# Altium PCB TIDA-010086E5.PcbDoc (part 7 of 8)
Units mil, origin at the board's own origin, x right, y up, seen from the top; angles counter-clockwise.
Board outline 6400 x 6200 mil, 6 copper layers (Top Layer, Power, AGND, Signal, PGND, Bottom Layer), stack 70.536 mil thick; 717 components, 376 nets, 2259 pads, 2183 vias.
Unrouted connection lines stored in the file: 1424.
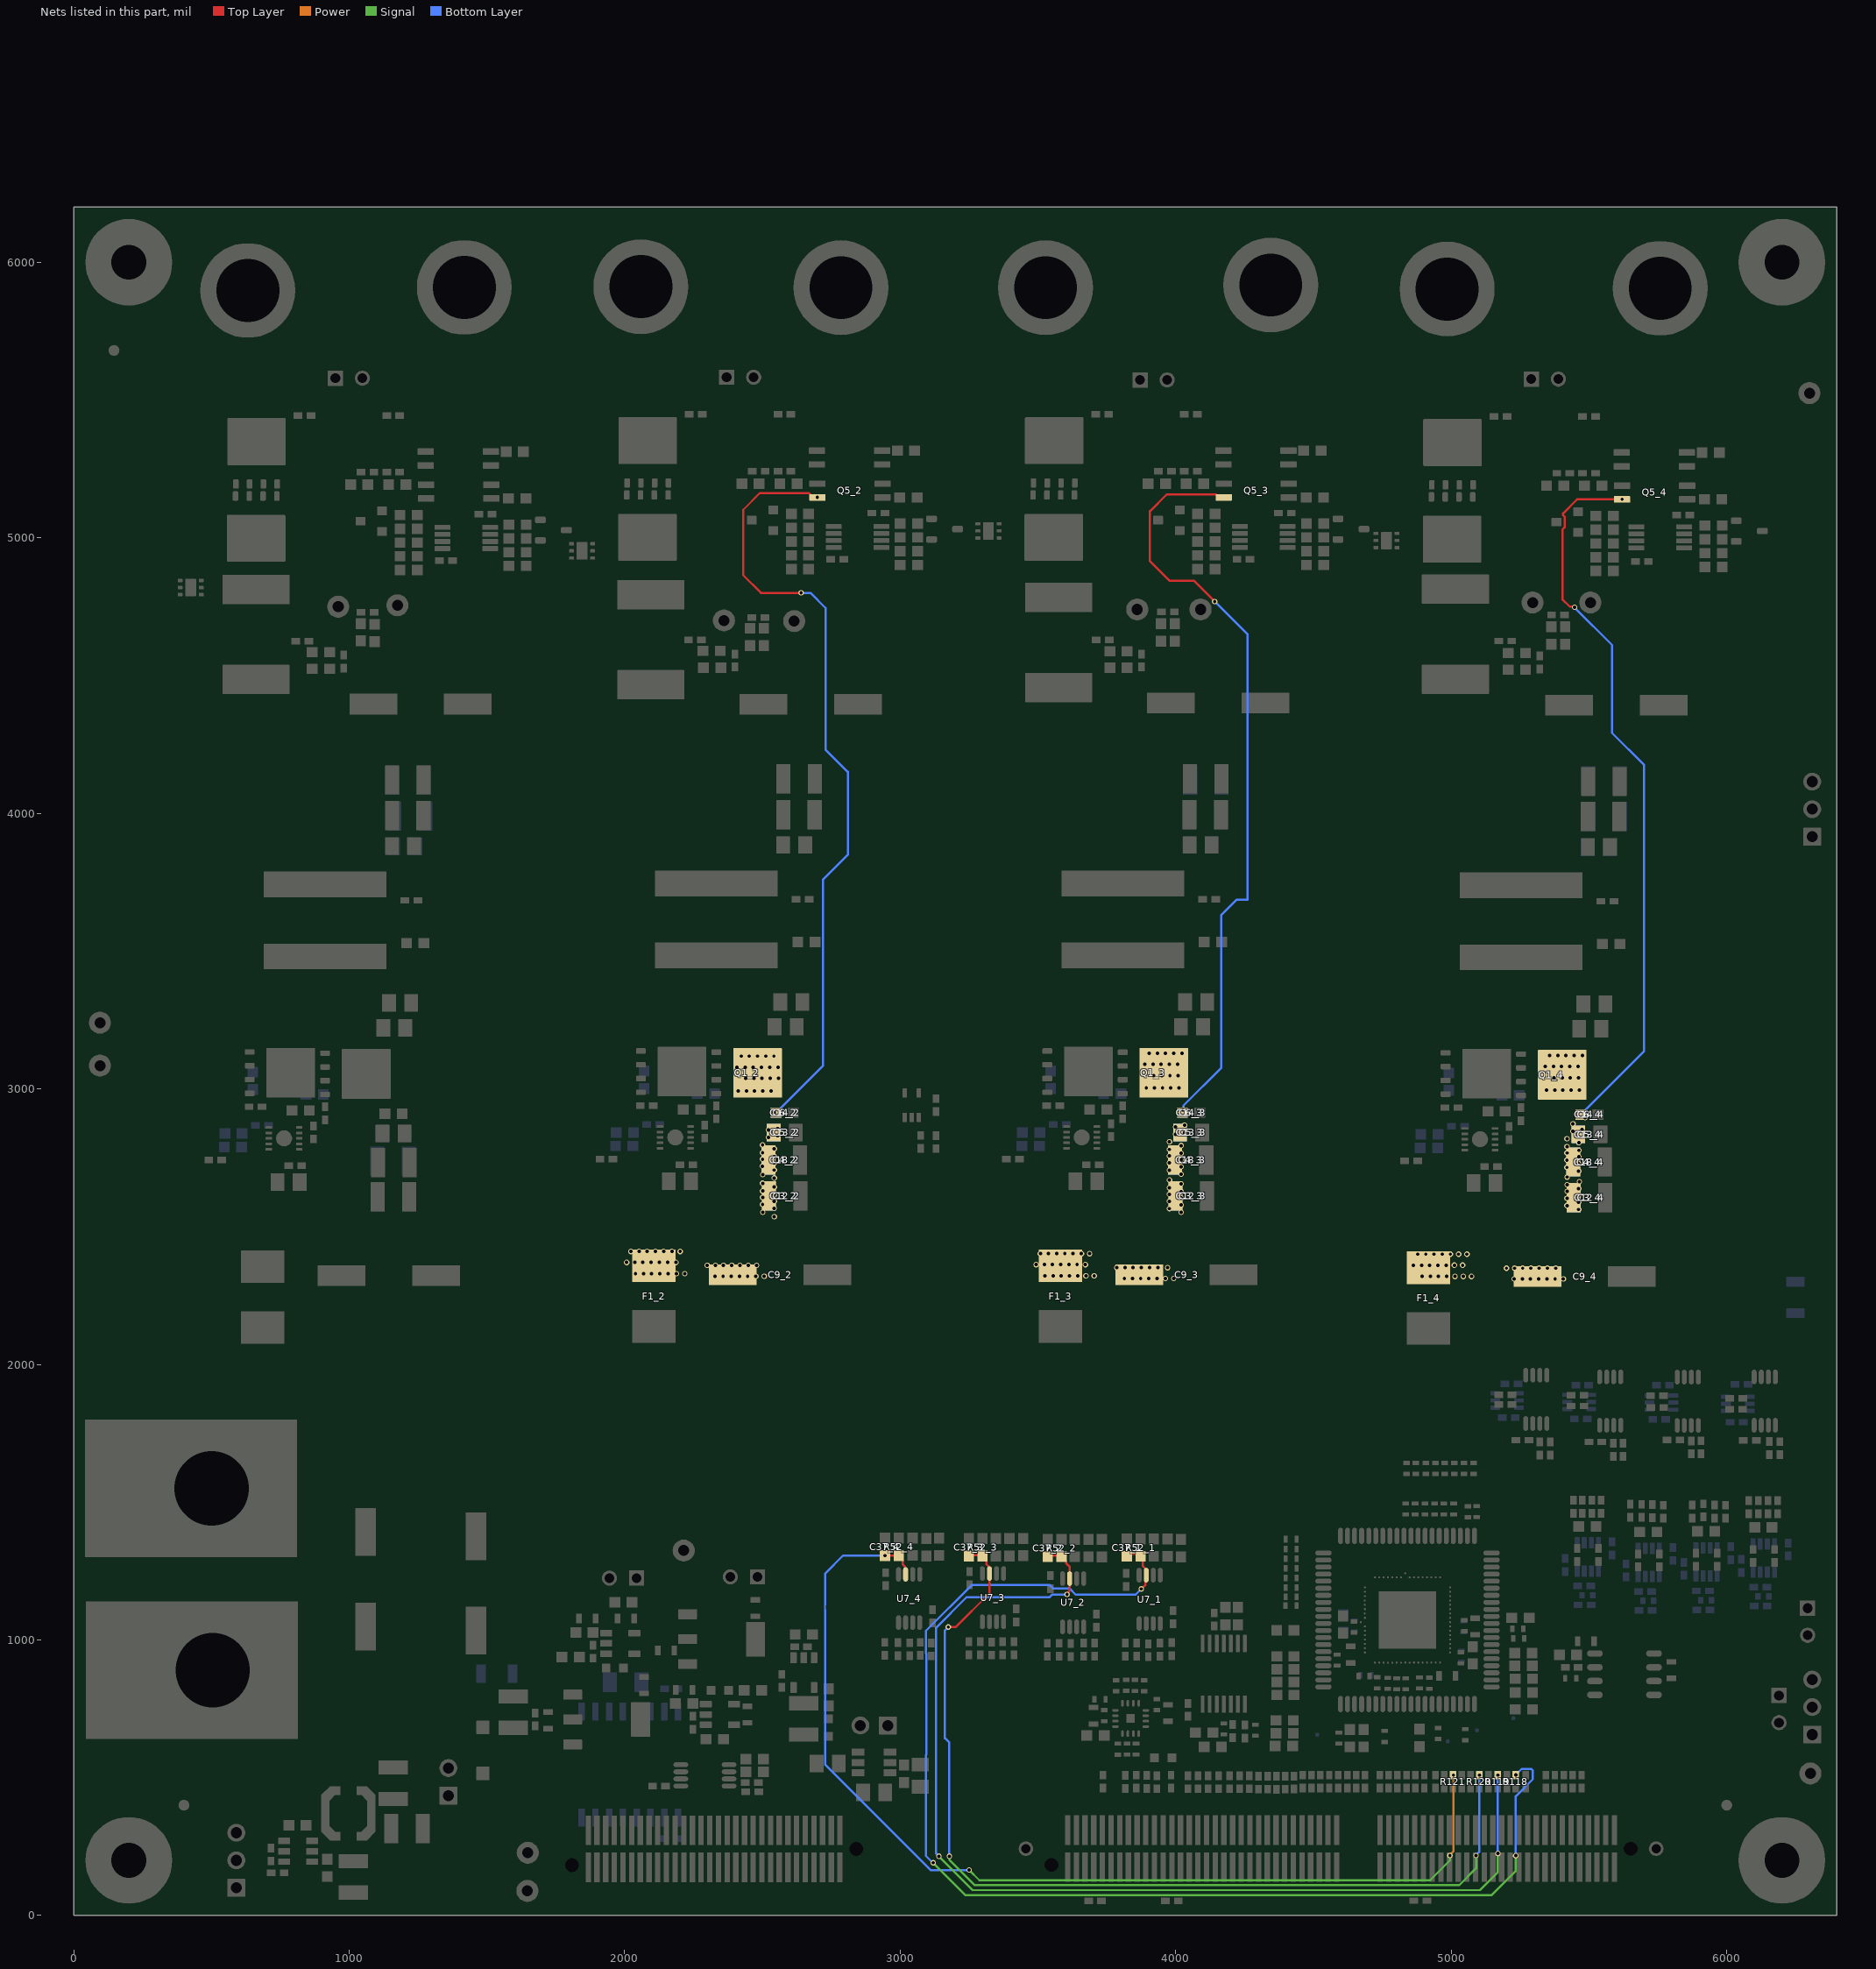
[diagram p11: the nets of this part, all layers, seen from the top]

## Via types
v1: diameter 20, hole 12.5, Top Layer to Bottom Layer, 1408 vias
v2: diameter 20, hole 12, Top Layer to Bottom Layer, tented both sides, 775 vias

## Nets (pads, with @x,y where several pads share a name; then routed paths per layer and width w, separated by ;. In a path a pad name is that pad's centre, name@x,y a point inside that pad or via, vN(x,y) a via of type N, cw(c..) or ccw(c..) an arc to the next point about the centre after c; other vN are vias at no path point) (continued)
VIN_2: C3_2.1 C4_2.1 C5_2.1 C6_2.1 C9_2.1 C12_2.1 C13_2.1 C14_2.1 C18_2.1 F1_2.1 Q1_2.5 Q1_2.6 Q1_2.7 Q1_2.8 Q1_2.9@2481.97,3057.91 Q5_2.4 | length 2861.8
  Top Layer w7.87: v2(2640,4800) 2494.23,4800 2430,4864.23 2430,5101.61 2490.35,5161.96 2668.85,5161.96 2674.71,5156.1 2674.71,5153.15 2681.2,5146.66 v2(2699.24,5146.66)
  Bottom Layer w7.87: C14_2.1@2549.17,2913.31 2550.16,2913.31 2564.92,2928.07 2564.92,2929.06 2720,3084.13 2720,3760 2810,3850 2810,4150 2728.35,4231.65 2728.35,4745.4 2673.75,4800 v2(2640,4800)
  other v1: 2327.28,2319.91 2356.97,2319.91 2386.1,2319.91 2416.1,2319.91 2446.1,2319.91 2476.1,2319.91 2506.1,2319.91 2038.86,2329.06 2068.54,2329.06 2097.68,2329.06 2127.68,2329.06 2157.68,2329.06 2187.68,2329.06 2217.68,2329.06 2299.53,2359.06 2329.21,2359.06 2358.35,2359.06 2388.35,2359.06 2418.35,2359.06 2448.35,2359.06 2478.35,2359.06 2006.83,2369.91 2036.52,2369.91 2065.65,2369.91 2095.65,2369.91 2125.65,2369.91 2155.65,2369.91 2185.65,2369.91 2022.28,2409.91 2051.97,2409.91 2081.1,2409.91 2111.1,2409.91 2141.1,2409.91 2171.1,2409.91 2201.1,2409.91 2542.93,2535.61 2500.89,2551.68 2542.43,2566.45 2500.12,2580.25 2542.68,2592.1 2500.37,2605.89 2542.68,2615.52 2500.37,2629.32 2542.68,2643.58 2500.37,2657.38 2542.93,2676.33 2500.89,2688.22 2542.68,2705.25 2499.87,2719.11 2542.93,2730.89 2500.12,2744.76 2542.93,2754.32 2500.12,2768.19 2542.93,2782.38 2500.12,2796.25 2521.81,2823.82 2554.99,2829.68 2521.81,2850.48 2554.99,2856.34 2541.62,2914.26 2412.07,2992.72 2441.76,2992.72 2470.89,2992.72 2500.89,2992.72 2530.89,2992.72 2439.18,3037.79 2468.87,3037.79 2498,3037.79 2528,3037.79 2558,3037.79 2407.15,3078.63 2436.84,3078.63 2465.97,3078.63 2495.97,3078.63 2525.97,3078.63 2555.97,3078.63 2422.61,3118.63 2452.29,3118.63 2481.43,3118.63 2511.43,3118.63 2541.43,3118.63
VIN_3: C3_3.1 C4_3.1 C5_3.1 C6_3.1 C9_3.1 C12_3.1 C13_3.1 C14_3.1 C18_3.1 F1_3.1 Q1_3.5 Q1_3.6 Q1_3.7 Q1_3.8 Q1_3.9@3956.97,3057.91 Q5_3.4 | length 2799.5
  Top Layer w7.87: v2(4141.48,4768.86) 4065.68,4844.66 3976.71,4844.66 3906.32,4915.04 3906.32,5096.44 3967.31,5157.43 4145.43,5157.43 4156.52,5146.34 Q5_3.4@4174.24,5146.34
  Bottom Layer w7.87: C14_3.1@4024.17,2913.31 4025.16,2913.31 C14_3.1@4030.83,2918.98 ; C14_3.1@4026.06,2925.01 C14_3.1@4027.04,2925.01 ; v1(4026.26,2923.56) 4028.24,2925.54 4028.24,2939.21 4165.29,3076.26 4165.29,3631.14 4219.99,3685.85 4260,3685.85 4260,4650.34 v2(4141.48,4768.86)
  other v1: 3813.58,2311.92 3843.27,2311.92 3872.4,2311.92 3902.4,2311.92 3932.4,2311.92 3962.4,2311.92 3992.4,2311.92 3525.16,2321.07 3554.84,2321.07 3583.98,2321.07 3613.98,2321.07 3643.98,2321.07 3673.98,2321.07 3703.98,2321.07 3785.83,2351.07 3815.51,2351.07 3844.65,2351.07 3874.65,2351.07 3904.65,2351.07 3934.65,2351.07 3970.3,2351.07 3493.13,2361.92 3522.81,2361.92 3551.95,2361.92 3581.95,2361.92 3611.95,2361.92 3641.95,2361.92 3671.95,2361.92 3508.58,2401.92 3538.27,2401.92 3567.4,2401.92 3597.4,2401.92 3627.4,2401.92 3657.4,2401.92 3687.4,2401.92 4019.32,2551.49 3977,2565.29 4019.32,2578.15 3977,2591.95 4019.56,2603.8 3977.25,2617.6 4019.56,2627.23 3977.25,2641.02 4019.56,2655.29 3977.25,2669.08 4019.56,2690.29 3976.75,2704.15 4019.56,2716.95 3976.75,2730.82 4019.81,2742.6 3977,2756.47 4019.81,2766.02 3977,2779.89 4019.81,2794.08 3977,2807.95 3998.7,2835.52 4031.88,2841.38 3998.7,2862.18 4031.88,2868.05 3893.05,3003.2 3922.74,3003.2 3951.87,3003.2 3981.87,3003.2 4011.87,3003.2 3920.16,3048.28 3949.84,3048.28 3978.98,3048.28 4008.98,3048.28 3888.13,3089.12 3917.81,3089.12 3946.95,3089.12 3976.95,3089.12 4006.95,3089.12 3903.58,3129.12 3933.27,3129.12 3962.4,3129.12 3992.4,3129.12 4022.4,3129.12
VIN_4: C3_4.1 C4_4.1 C5_4.1 C6_4.1 C9_4.1 C12_4.1 C13_4.1 C14_4.1 C18_4.1 F1_4.1 Q1_4.5 Q1_4.6 Q1_4.7 Q1_4.8 Q1_4.9@5402.75,3051.07 Q5_4.4 | length 2651.1
  Top Layer w7.87: v2(5447.82,4747.79) 5445.5,4750.11 5430.17,4750.11 5403.59,4776.68 5403.59,5030.09 5411.16,5037.66 5411.16,5076.54 5405.56,5082.14 5405.56,5088.66 5456.4,5139.5 Q5_4.4@5620.02,5139.5 v2(5620.02,5139.82)
  Bottom Layer w7.87: v2(5447.82,4747.79) 5447.82,4746.6 5583.34,4611.09 5583.34,4291.66 5700,4175 5700,3136.52 5485.7,2922.22 5485.7,2921.23 5470.94,2906.47 C14_4.1@5469.95,2906.47
  other v1: 5227.96,2310 5257.65,2310 5286.78,2310 5316.78,2310 5346.78,2310 5376.78,2310 5406.78,2310 4894.54,2319.15 4924.22,2319.15 4953.36,2319.15 4983.36,2319.15 5013.36,2319.15 5043.36,2319.15 5073.36,2319.15 5200.21,2349.15 5229.89,2349.15 5259.03,2349.15 5289.03,2349.15 5319.03,2349.15 5349.03,2349.15 5379.03,2349.15 4862.51,2360 4892.19,2360 4921.33,2360 4951.33,2360 4981.33,2360 5011.33,2360 5041.33,2360 4877.96,2400 4907.65,2400 4936.78,2400 4966.78,2400 4996.78,2400 5026.78,2400 5056.78,2400 5462.26,2562.22 5419.95,2576.02 5462.26,2588.88 5419.95,2602.68 5462.51,2614.53 5420.2,2628.33 5462.51,2637.95 5420.2,2651.75 5465.12,2663.08 5420.2,2679.81 5462.51,2701.02 5419.7,2714.88 5462.51,2727.68 5419.7,2741.54 5462.76,2753.33 5419.95,2767.19 5462.76,2776.75 5419.95,2790.62 5462.76,2804.81 5419.95,2818.68 5441.64,2846.25 5474.82,2852.11 5441.64,2872.91 5485.7,2895.83 5346.3,2995.29 5375.98,2995.29 5405.12,2995.29 5435.12,2995.29 5465.12,2995.29 5373.4,3040.36 5403.09,3040.36 5432.22,3040.36 5462.22,3040.36 5341.38,3081.21 5371.06,3081.21 5400.19,3081.21 5430.19,3081.21 5460.19,3081.21 5356.83,3121.21 5386.51,3121.21 5415.65,3121.21 5445.65,3121.21 5475.65,3121.21
VoutP1: C37_1.1 R52_1.2 R118.1 U7_1.7 | length 4585.6
  Top Layer w7.87: C37_1.1@3816.27,1311.67 3866.27,1311.67 3879.97,1297.97 3879.97,1268.78 3890.62,1258.13 3890.62,1236.77 U7_1.7@3892.5,1234.89 3890.62,1233 3890.62,1200.62 v2(3875,1185)
  Signal w7.87: v2(3119.71,190.92) 3119.71,189.79 3235.63,73.87 5146.41,73.87 5234.07,161.53 v2(5234.07,216.97)
  Bottom Layer w7.87: v2(3119.71,190.92) 3118.58,190.92 3093.24,216.26 3093.24,582.77 3094.21,583.74 3094.21,950.25 3093.24,951.22 3093.24,1032.77 3259.33,1198.85 3542.46,1198.85 3554.51,1186.81 3614.03,1186.81 3636.61,1164.24 3854.24,1164.24 v2(3875,1185) ; v2(5234.07,216.97) 5233.87,217.17 5233.87,432.45 5295.53,494.11 5295.53,526.16 5289.68,532.02 5255.99,532.02 v2(5234.07,510.1)
VoutP2: C37_2.1 R52_2.2 R119.1 U7_2.7 | length 4024.4
  Top Layer w7.87: C37_2.1@3537.7,1306.09 3587.7,1306.09 3587.7,1298.55 3602.44,1283.81 3602.44,1277.5 3609.35,1270.58 3610.05,1270.58 3614.67,1265.97 U7_2.7@3614.67,1222.56 3614.67,1177.91 3605,1168.25 v2(3605,1165)
  Signal w7.87: v2(3140,214.63) 3262.88,91.75 5103.62,91.75 5168.92,157.05 v2(5168.92,225)
  Bottom Layer w7.87: v2(3140,214.63) 3140,215.3 3130,225.3 3130,1044.25 3240.98,1155.23 3542.46,1155.23 3552.23,1165 v2(3605,1165) ; v2(5168.92,225) v2(5168.92,509.13)
VoutP3: C37_3.1 R52_3.2 R120.1 U7_3.7 | length 3573
  Top Layer w7.87: v2(3174.16,1046.42) 3201.06,1046.42 3323.72,1169.08 U7_3.7@3323.72,1241.1 ; C37_3.1@3248.72,1307.07 3298.72,1307.07 3312.42,1293.37 3312.42,1275.39 3322.24,1265.57 U7_3.7@3322.24,1241.1
  Signal w7.87: v2(3178.14,214.63) 3179.39,213.38 3179.39,200.52 3200.46,179.45 3270.29,109.62 5028.56,109.62 5090,171.06 v2(5090,217.27)
  Bottom Layer w7.87: v2(3174.16,1046.42) 3162.02,1034.28 3162.02,643.51 3178.14,627.39 v2(3178.14,214.63) ; v2(5090,217.27) 5090,219.98 5102.07,232.05 v2(5102.07,509.13)
VoutP4: C37_4.1 R52_4.2 R121.1 U7_4.7 | length 3852.8
  Top Layer w7.87: v2(2944.4,1306.09) R52_4.2@2994.39,1306.09 3009.16,1291.32 3009.16,1273.34 3017.51,1264.99 3017.51,1239.79 U7_4.7@3019.39,1237.91
  Signal w7.87: v2(3250,165) 3287.37,127.63 4922.95,127.63 4995,199.69 v2(4995,217.27)
  Power w7.87: v2(4995,217.27) 4995,219.98 5008.04,233.02 v2(5008.04,509.13)
  Bottom Layer w7.87: v2(2944.4,1306.09) 2792.83,1306.09 2727.87,1241.12 2727.87,1128.6 2726.74,1127.47 2726.74,1108.52 2727.87,1107.39 2727.87,546.82 3109.95,164.75 3249.75,164.75 v2(3250,165)
pads on no net: FID1.1 FID2.1 FID3.1 H1.1 H2.1 H3.1 H4.1 H5.0 H6.0 H7.0 H8.0 J13.1 J13.2 J13.3 J13.4 J13.5 J13.6 J13.8 J13.9 J13.11 J13.14 J13.17 J13.20 J13.23 J13.24 J13.26 J13.27 J13.32 J13.34 J13.36 J13.40 J13.41 J13.42 J13.43 J13.44 J13.58 J13.60 J13.62 J13.63 J13.64 J13.66 J13.76 J13.78 J13.86 J13.88 J13.89 J13.90 J13.91 J13.92 J13.93 J13.94 J13.95 J13.106 J13.107 J13.108 J13.109 J13.110 J13.113 J13.114 J13.115 J13.116 J13.117 J13.118 J13.119 J13.120 J13.181 J13.182 J13.185 J13.186 J14.61 J14.62 J14.121 J14.122 J14.123 J14.124 J14.125 J14.126 J14.127 J14.128 J14.129 J14.130 J14.131 J14.132 J14.133 J14.134 J14.136 J14.137 J14.138 J14.139 J14.140 J14.141 J14.142 J14.143 J14.144 J14.145 J14.146 J14.147 J14.148 J14.149 J14.150 J14.151 J14.152 J14.153 J14.154 J14.155 J14.156 J14.159 J14.160 J14.161 J14.162 J14.163 J14.164 J14.165 J14.166 J14.167 J14.168 J14.169 J14.170 J14.171 J14.172 J14.173 J14.174 J14.175 J14.176 J14.177 J14.178 LBL1.0 Q1_1.9@1007.32,2997.24 Q1_1.9@1007.32,3054.33 Q1_1.9@1007.32,3111.42 Q1_1.9@1043.94,3054.33 Q1_1.9@1077.4,2997.24 Q1_1.9@1077.4,3054.33 Q1_1.9@1077.4,3111.42 Q1_2.9@2427.44,3000.83 Q1_2.9@2427.44,3057.91 Q1_2.9@2427.44,3115 Q1_2.9@2464.06,3057.91 Q1_2.9@2497.52,3000.83 Q1_2.9@2497.52,3057.91 Q1_2.9@2497.52,3115 Q1_3.9@3902.44,3000.83 Q1_3.9@3902.44,3057.91 Q1_3.9@3902.44,3115 Q1_3.9@3939.06,3057.91 Q1_3.9@3972.52,3000.83 Q1_3.9@3972.52,3057.91 Q1_3.9@3972.52,3115 Q1_4.9@5348.22,2993.99 Q1_4.9@5348.22,3051.07 Q1_4.9@5348.22,3108.16 Q1_4.9@5384.83,3051.07 Q1_4.9@5418.3,2993.99 Q1_4.9@5418.3,3051.07 Q1_4.9@5418.3,3108.16 Q2_1.9@568.72,5073.35 Q2_1.9@609.76,4971.18 Q2_1.9@609.76,5016.46 Q2_1.9@609.76,5061.73 Q2_1.9@662.13,4971.18 Q2_1.9@662.13,5011.14 Q2_1.9@662.13,5016.46 Q2_1.9@662.13,5061.73 Q2_1.9@714.49,4971.18 Q2_1.9@714.49,5016.46 Q2_1.9@714.49,5061.73 Q2_1.9@755.53,5073.35 Q2_2.9@1988.84,5076.93 Q2_2.9@2029.88,4974.76 Q2_2.9@2029.88,5020.04 Q2_2.9@2029.88,5065.31 Q2_2.9@2082.24,4974.76 Q2_2.9@2082.24,5014.72 Q2_2.9@2082.24,5020.04 Q2_2.9@2082.24,5065.31 Q2_2.9@2134.61,4974.76 Q2_2.9@2134.61,5020.04 Q2_2.9@2134.61,5065.31 Q2_2.9@2175.65,5076.93 Q2_3.9@3463.84,5076.93 Q2_3.9@3504.88,4974.76 Q2_3.9@3504.88,5020.04 Q2_3.9@3504.88,5065.31 Q2_3.9@3557.24,4974.76 Q2_3.9@3557.24,5014.72 Q2_3.9@3557.24,5020.04 Q2_3.9@3557.24,5065.31 Q2_3.9@3609.61,4974.76 Q2_3.9@3609.61,5020.04 Q2_3.9@3609.61,5065.31 Q2_3.9@3650.65,5076.93 Q2_4.9@4909.62,5070.09 Q2_4.9@4950.66,4967.93 Q2_4.9@4950.66,5013.2 Q2_4.9@4950.66,5058.48 Q2_4.9@5003.02,4967.93 Q2_4.9@5003.02,5007.89 Q2_4.9@5003.02,5013.2 Q2_4.9@5003.02,5058.48 Q2_4.9@5055.39,4967.93 Q2_4.9@5055.39,5013.2 Q2_4.9@5055.39,5058.48 Q2_4.9@5096.43,5070.09 Q3_1.9@570.06,5273.74 Q3_1.9@611.1,5285.35 Q3_1.9@611.1,5330.63 Q3_1.9@611.1,5375.91 Q3_1.9@663.46,5285.35 Q3_1.9@663.46,5330.63 Q3_1.9@663.46,5335.94 Q3_1.9@663.46,5375.91 Q3_1.9@715.83,5285.35 Q3_1.9@715.83,5330.63 Q3_1.9@715.83,5375.91 Q3_1.9@756.87,5273.74 Q3_2.9@1990.18,5277.32 Q3_2.9@2031.22,5288.94 Q3_2.9@2031.22,5334.21 Q3_2.9@2031.22,5379.49 Q3_2.9@2083.58,5288.94 Q3_2.9@2083.58,5334.21 Q3_2.9@2083.58,5339.53 Q3_2.9@2083.58,5379.49 Q3_2.9@2135.95,5288.94 Q3_2.9@2135.95,5334.21 Q3_2.9@2135.95,5379.49 Q3_2.9@2176.99,5277.32 Q3_3.9@3465.18,5277.32 Q3_3.9@3506.22,5288.94 Q3_3.9@3506.22,5334.21 Q3_3.9@3506.22,5379.49 Q3_3.9@3558.58,5288.94 Q3_3.9@3558.58,5334.21 Q3_3.9@3558.58,5339.53 Q3_3.9@3558.58,5379.49 Q3_3.9@3610.94,5288.94 Q3_3.9@3610.94,5334.21 Q3_3.9@3610.94,5379.49 Q3_3.9@3651.99,5277.32 Q3_4.9@4910.96,5270.48 Q3_4.9@4952,5282.1 Q3_4.9@4952,5327.37 Q3_4.9@4952,5372.65 Q3_4.9@5004.36,5282.1 Q3_4.9@5004.36,5327.37 Q3_4.9@5004.36,5332.69 Q3_4.9@5004.36,5372.65 Q3_4.9@5056.72,5282.1 Q3_4.9@5056.72,5327.37 Q3_4.9@5056.72,5372.65 Q3_4.9@5097.77,5270.48 Q4_1.9@733.5,3001.77 Q4_1.9@733.5,3058.86 Q4_1.9@733.5,3115.94 Q4_1.9@770.12,3058.86 Q4_1.9@803.58,3001.77 Q4_1.9@803.58,3058.86 Q4_1.9@803.58,3115.94 Q4_2.9@2153.62,3005.35 Q4_2.9@2153.62,3062.44 Q4_2.9@2153.62,3119.53 Q4_2.9@2190.24,3062.44 Q4_2.9@2223.7,3005.35 Q4_2.9@2223.7,3062.44 Q4_2.9@2223.7,3119.53 Q4_3.9@3628.62,3005.35 Q4_3.9@3628.62,3062.44 Q4_3.9@3628.62,3119.53 Q4_3.9@3665.24,3062.44 Q4_3.9@3698.7,3005.35 Q4_3.9@3698.7,3062.44 Q4_3.9@3698.7,3119.53 Q4_4.9@5074.4,2998.52 Q4_4.9@5074.4,3055.6 Q4_4.9@5074.4,3112.69 Q4_4.9@5111.02,3055.6 Q4_4.9@5144.48,2998.52 Q4_4.9@5144.48,3055.6 Q4_4.9@5144.48,3112.69 R151.1 SH-J1.0 SH-J2.0 SH-J3.0 U1_1.7@424.52,4801.64 U1_1.7@424.52,4837.07 U1_2.7@1845,4935 U1_2.7@1845,4970.43 U1_3.7@3320,5007.28 U1_3.7@3320,5042.72 U1_4.7@4765,4972.28 U1_4.7@4765,5007.72 U3_1.2 U3_2.2 U3_3.2 U3_4.2 U5_1.1 U5_2.1 U5_3.1 U5_4.1 U6_1.2 U6_1.3 U6_2.2 U6_2.3 U6_3.2 U6_3.3 U6_4.2 U6_4.3 U9.4 U11.4 U15.41 U15.42 U15.43 U15.44 U15.45 U15.46 U18.1 U18.3 U18.7 U18.8 U20.1 U20.5 U22.4 U22.5 U22.11 U22.14

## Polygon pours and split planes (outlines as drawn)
PGND on Top Layer "TOP_LAYER_PGND_P274" (solid, remove dead copper, pour order 274): 0,6173.76 0,3.76 1510.39,3.76 1519.56,1646.22 4659.4,1646.22 5224.69,2203.76 6400,2203.76 6400,6203.71
5VD on Top Layer "TOP_LAYER_5VD_P127" (solid, remove dead copper, pour order 127): 2434.66,1100.2 2434.66,920.74 2637.87,920.74 2637.87,1100.2
AGND on Top Layer "TOP_LAYER_AGND_P273" (solid, remove dead copper, pour order 273): 1515,2227.77 1515,0.95 6400,0.95 6400,2227.77
Source_1 on Top Layer "TOP_LAYER_SOURCE_1_P272" (solid, remove dead copper, pour order 272): 454.52,5229.08 454.52,5124.49 893.97,5124.49 893.97,5229.08
SW_1 on Top Layer "TOP_LAYER_SW_1_P130" (solid, remove dead copper, pour order 130): 950,3156.51 950,3009.08 893.82,3009.08 890,3005.27 890,2964.08 818.54,2964.08 818.54,2900 770.12,2900 772.84,2959.79 697.57,2974.08 694.02,3061.22 694.02,3147.63 545.07,3296.58 545.07,3642.84 1241.48,3642.84 1241.48,3364.08 1110,3364.08 1110,3270 1135.12,3270 1162.57,3242.55 1162.57,3174.08 967.57,3174.08
V_HV on Top Layer "V_HV_Top" (solid, remove dead copper, pour order 143): 27.16,2235.04 27.16,1290 1836.73,1290 2236.54,1660 4633.7,1660 4910.47,1936.77 5002.69,2045 4999.96,2235.04
VIN_4 on Top Layer "TOP_LAYER_VIN_4_P136" (solid, remove dead copper, pour order 136): 4917.42,2580.83 4805.42,2527.49 4805.42,2246.66 4804.58,2245.83 5495.42,2245.83 5495.42,3153.04 5290.42,3153.04 5290.42,2580.83
VIN_3 on Top Layer "TOP_LAYER_VIN_3_P137" (solid, remove dead copper, pour order 137): 3471.64,2587.67 3359.64,2534.33 3359.64,2253.5 3359.64,2235.04 4049.64,2235.04 4049.64,3159.87 3844.64,3159.87 3844.64,2587.67
VIN_2 on Top Layer "TOP_LAYER_VIN_2_P140" (solid, remove dead copper, pour order 140): 1994.88,2590.11 1882.88,2536.78 1882.88,2255.94 1882.05,2255.11 2572.88,2255.11 2572.88,3162.32 2367.88,3162.32 2367.88,2590.11
VIN_1 on Top Layer "TOP_LAYER_VIN_1_P134" (solid, remove dead copper, pour order 134): 576.52,2584.08 464.52,2530.75 464.52,2249.91 463.69,2249.08 1154.52,2249.08 1154.52,3156.29 959.97,3156.29 959.97,2584.08
10VA on Top Layer "TOP_LAYER_10VA_P144" (solid, remove dead copper, pour order 144): 1482.03,5097.4 1482.03,5060.04 1482.03,5027.76 1542.51,5027.76 1542.51,5097.4
-5VA on Top Layer "TOP_LAYER_-5VA_P145" (solid, remove dead copper, pour order 145): 4204.47,4974.11 4204.47,4907.11 4264.64,4907.11 4264.64,4974.11
NetR28_1_1 on Top Layer "TOP_LAYER_NETR28_1_1_P146" (solid, remove dead copper, pour order 146): 1477.03,4998.15 1538.52,4998.15 1557.34,5016.97 1601.76,5016.97 1601.76,4925.62 1599.28,4925.62 1558.07,4925.62 1558.07,4952.99 1540.54,4970.53 1477.03,4970.53 1477.03,4997.76
NetR28_2_1 on Top Layer "TOP_LAYER_NETR28_2_1_P147" (solid, remove dead copper, pour order 147): 2897.15,5001.73 2960.73,5001.73 2985.54,5026.54 3021.87,5026.54 3021.87,4929.2 3019.4,4929.2 2978.19,4929.2 2978.19,4956.57 2960.65,4974.11 2897.15,4974.11 2897.15,5001.34
NetR28_3_1 on Top Layer "TOP_LAYER_NETR28_3_1_P148" (solid, remove dead copper, pour order 148): 4372.15,5001.73 4435.73,5001.73 4460.54,5026.54 4496.87,5026.54 4496.87,4929.2 4494.4,4929.2 4453.19,4929.2 4453.19,4956.57 4435.65,4974.11 4372.15,4974.11 4372.15,5001.34
NetR28_4_1 on Top Layer "TOP_LAYER_NETR28_4_1_P149" (solid, remove dead copper, pour order 149): 5817.93,4994.89 5881.51,4994.89 5906.31,5019.7 5942.65,5019.7 5942.65,4922.37 5940.18,4922.37 5898.97,4922.37 5898.97,4949.73 5881.43,4967.27 5817.93,4967.27 5817.93,4994.5
10VA on Top Layer "TOP_LAYER_10VA_P151" (solid, remove dead copper, pour order 151): 2902.15,5104.74 2902.15,5063.62 2902.15,5031.34 2962.63,5031.34 2962.63,5104.74
10VA on Top Layer "TOP_LAYER_10VA_P152" (solid, remove dead copper, pour order 152): 4377.15,5100.77 4377.15,5063.62 4377.15,5031.34 4437.63,5031.34 4437.63,5100.77
10VA on Top Layer "TOP_LAYER_10VA_P153" (solid, remove dead copper, pour order 153): 5822.93,5104.62 5822.93,5056.78 5822.93,5024.5 5883.41,5024.5 5883.41,5104.62
5VA on Top Layer "TOP_LAYER_5VA_P154" (solid, remove dead copper, pour order 154): 1094.55,5114.08 1094.55,5071.98 1094.55,5063.35 1204.2,5063.35 1204.2,5114.08
5VA on Top Layer "TOP_LAYER_5VA_P155" (solid, remove dead copper, pour order 155): 3989.67,5117.67 3989.67,5075.56 3989.67,5066.93 4099.32,5066.93 4099.32,5117.67
5VA on Top Layer "TOP_LAYER_5VA_P156" (solid, remove dead copper, pour order 156): 5435.45,5110.83 5435.45,5068.72 5435.45,5060.09 5545.1,5060.09 5545.1,5110.83
-5VA on Top Layer "TOP_LAYER_-5VA_P157" (solid, remove dead copper, pour order 157): 1309.35,4970.53 1309.35,4903.53 1369.52,4903.53 1369.52,4970.53
-5VA on Top Layer "TOP_LAYER_-5VA_P158" (solid, remove dead copper, pour order 158): 2729.47,4974.11 2729.47,4907.11 2789.64,4907.11 2789.64,4974.11
-5VA on Top Layer "TOP_LAYER_-5VA_P159" (solid, remove dead copper, pour order 159): 5650.25,4967.27 5650.25,4900.27 5710.42,4900.27 5710.42,4967.27
NetC43_1 on Top Layer "TOP_LAYER_NETC43_1_P160" (solid, remove dead copper, pour order 160): 1070,172.84 1070,245 1127.64,245 843.71,245 845,170
NetC40_1 on Top Layer "TOP_LAYER_NETC40_1_P132" (solid, remove dead copper, pour order 132): 995,254.32 995,475 823.34,475 823.34,254.32
NetC41_1 on Top Layer "TOP_LAYER_NETC41_1_P131" (solid, remove dead copper, pour order 131): 1200,255.51 1200,475.37 1005,475.37 1005,255.51
NetC54_2 on Top Layer "TOP_LAYER_NETC54_2_P161" (solid, remove dead copper, pour order 161): 2228.49,721.45 2228.49,619.54 2313.9,619.54 2313.9,721.45
3V3A on Top Layer "TOP_LAYER_3V3A_P162" (solid, remove dead copper, pour order 162): 2519.57,835.56 2475.12,835.56 2475.12,785 2374.25,785 2374.25,745 2519.57,745 2519.57,792.9
-5VA on Top Layer "TOP_LAYER_-5VA_P163" (solid, remove dead copper, pour order 163): 3059.13,1092.99 3059.13,1035.28 3130,1035.28 3130,1092.99
10VA on Top Layer "TOP_LAYER_10VA_P164" (solid, remove dead copper, pour order 164): 2929.45,1277.5 2929.45,1212.5 3005,1212.5 3005,1277.5
NetR45_4_2 on Top Layer "TOP_LAYER_NETR45_4_2_P165" (solid, remove dead copper, pour order 165): 3062.16,1324.52 3062.16,1212.5 3155,1212.5 3155,1324.52
10VA on Top Layer "TOP_LAYER_10VA_P166" (solid, remove dead copper, pour order 166): 3233.77,1278.49 3233.77,1213.49 3309.32,1213.49 3309.32,1278.49
NetR45_3_2 on Top Layer "TOP_LAYER_NETR45_3_2_P167" (solid, remove dead copper, pour order 167): 3366.49,1325.51 3366.49,1213.49 3459.32,1213.49 3459.32,1325.51
-5VA on Top Layer "TOP_LAYER_-5VA_P169" (solid, remove dead copper, pour order 169): 3360.27,1092.99 3360.27,1035.28 3431.14,1035.28 3431.14,1092.99
-5VA on Top Layer "TOP_LAYER_-5VA_P171" (solid, remove dead copper, pour order 171): 3652.44,1075 3652.44,1021.33 3723.3,1021.33 3723.3,1075
-5VA on Top Layer "TOP_LAYER_-5VA_P172" (solid, remove dead copper, pour order 172): 3931,1086.75 3931,1029.05 4001.87,1029.05 4001.87,1086.75
10VA on Top Layer "TOP_LAYER_10VA_P185" (solid, remove dead copper, pour order 185): 3524.39,1263.93 3524.39,1198.93 3599.95,1198.93 3599.95,1263.93
NetR45_2_2 on Top Layer "TOP_LAYER_NETR45_2_2_P190" (solid, remove dead copper, pour order 190): 3662.16,1323.35 3662.16,1199.62 3755,1199.62 3755,1323.35
10VA on Top Layer "TOP_LAYER_10VA_P191" (solid, remove dead copper, pour order 191): 3800.12,1269.15 3800.12,1204.15 3875.67,1204.15 3875.67,1269.15
NetR45_1_2 on Top Layer "TOP_LAYER_NETR45_1_2_P192" (solid, remove dead copper, pour order 192): 3934.94,1323.35 3934.94,1211.33 4040,1211.33 4040,1323.35
NetC31_1_2 on Top Layer "TOP_LAYER_NETC31_1_2_P195" (solid, remove dead copper, pour order 195): 6069.41,1413 6069.41,1421.33 6069.41,1311.97 6126.15,1311.97 6126.15,1474.47 6069.41,1474.47
NetC28_1_2 on Top Layer "TOP_LAYER_NETC28_1_2_P197" (solid, remove dead copper, pour order 197): 6135.69,1415.13 6135.69,1423.46 6135.69,1314.1 6194.41,1314.1 6194.41,1476.6 6135.69,1476.6
NetC31_2_2 on Top Layer "TOP_LAYER_NETC31_2_2_P198" (solid, remove dead copper, pour order 198): 5859.95,1401.7 5859.95,1410.04 5859.95,1300.67 5916.7,1300.67 5916.7,1463.17 5859.95,1463.17
NetC28_2_2 on Top Layer "TOP_LAYER_NETC28_2_2_P204" (solid, remove dead copper, pour order 204): 5926.24,1403.83 5926.24,1412.17 5926.24,1302.8 5993.72,1302.8 5993.72,1465.3 5926.24,1465.3
NetC31_3_2 on Top Layer "TOP_LAYER_NETC31_3_2_P205" (solid, remove dead copper, pour order 205): 5649.56,1397.53 5649.56,1405.87 5649.56,1296.51 5706.3,1296.51 5706.3,1459.01 5649.56,1459.01
NetC28_3_2 on Top Layer "TOP_LAYER_NETC28_3_2_P207" (solid, remove dead copper, pour order 207): 5715.84,1399.66 5715.84,1408 5715.84,1298.64 5774.56,1298.64 5774.56,1461.14 5715.84,1461.14
NetC31_4_2 on Top Layer "TOP_LAYER_NETC31_4_2_P208" (solid, remove dead copper, pour order 208): 5430.56,1419.36 5430.56,1427.69 5430.56,1318.33 5487.31,1318.33 5487.31,1480.83 5430.56,1480.83
NetC28_4_2 on Top Layer "TOP_LAYER_NETC28_4_2_P209" (solid, remove dead copper, pour order 209): 5496.85,1421.49 5496.85,1429.82 5496.85,1320.46 5555.56,1320.46 5555.56,1482.96 5496.85,1482.96
5VA on Top Layer "TOP_LAYER_5VA_P210" (solid, remove dead copper, pour order 210): 5705.34,880.42 5705.34,839.57 5819.89,839.57 5819.89,880.42
10VA on Top Layer "TOP_LAYER_10VA_P213" (solid, remove dead copper, pour order 213): 2148.39,990.59 2148.39,888.68 2268.7,888.68 2268.7,990.59
10VA on Top Layer "TOP_LAYER_10VA_P129" (solid, remove dead copper, pour order 129): 1460,707.18 1460,606.73 1846.68,606.73 1846.68,707.18
5VA on Top Layer "TOP_LAYER_5VA_P215" (solid, remove dead copper, pour order 215): 1766.73,784.97 1766.73,648.17 2096.71,648.17 2096.71,784.97
5VA on Top Layer "TOP_LAYER_5VA_P224" (solid, remove dead copper, pour order 224): 2216.14,792.9 2216.14,748.21 2325,748.21 2325,792.9
ILN1 on Top Layer "TOP_LAYER_ILN1_P226" (solid, remove dead copper, pour order 226): 537.04,3636.57 1184.52,3636.57 1219.52,3654.08 1219.52,3749.08 1184.52,3764.08 1184.52,4474.08 908.97,4474.08 893.97,4489.08 893.97,4554.08 531.98,4554.08
LOCSEN_P1 on Top Layer "TOP_LAYER_LOCSEN_P1_P229" (solid, remove dead copper, pour order 229): 454.52,4750 893.97,4750 893.97,5084.63 859.04,5119.56 454.52,5119.56 454.52,4869.08
BATP_1 on Top Layer "TOP_LAYER_BATP_1_P230" (solid, remove dead copper, pour order 230): 848.52,5246.56 848.52,6137.88 423.52,6137.88 423.52,5246.56
SW_2 on Top Layer "TOP_LAYER_SW_2_P231" (solid, remove dead copper, pour order 231): 2359.64,3152.67 2359.64,3007.67 2305.88,3007.67 2299.64,3001.42 2299.64,2962.67 2238.66,2962.67 2238.66,2902.67 2190.43,2902.67 2189.48,2957.51 2109.64,2972.67 2106.09,3059.8 2106.09,3146.21 1957.14,3295.16 1957.14,3641.43 2653.54,3641.43 2653.54,3362.67 2523.58,3362.67 2523.58,3272.67 2554.64,3272.67 2574.64,3252.67 2574.64,3172.67 2379.64,3172.67
ILN2 on Top Layer "TOP_LAYER_ILN2_P232" (solid, remove dead copper, pour order 232): 1957.16,3640.16 2604.64,3640.16 2639.64,3657.67 2639.64,3752.67 2604.64,3767.67 2604.64,4477.67 2329.09,4477.67 2314.09,4492.67 2314.09,4557.67 1952.1,4557.67
LOCSEN_P2 on Top Layer "TOP_LAYER_LOCSEN_P2_P233" (solid, remove dead copper, pour order 233): 1874.64,4723.26 2314.09,4723.26 2314.09,5090.19 2274.23,5130.05 1874.64,5130.05 1874.64,4874.65
Source_2 on Top Layer "TOP_LAYER_SOURCE_2_P237" (solid, remove dead copper, pour order 237): 1874.64,5232.67 1874.64,5108.14 2314.09,5108.14 2314.09,5232.67
BATP_2 on Top Layer "TOP_LAYER_BATP_2_P240" (solid, remove dead copper, pour order 240): 2264.64,5241.34 2264.64,6132.67 1839.64,6132.67 1839.64,5241.34
BATP_3 on Top Layer "TOP_LAYER_BATP_3_P241" (solid, remove dead copper, pour order 241): 3739.64,5241.34 3739.64,6132.67 3314.64,6132.67 3314.64,5241.34
Source_3 on Top Layer "TOP_LAYER_SOURCE_3_P242" (solid, remove dead copper, pour order 242): 3349.64,5232.67 3349.64,5108.14 3789.09,5108.14 3789.09,5232.67
LOCSEN_P3 on Top Layer "TOP_LAYER_LOCSEN_P3_P133" (solid, remove dead copper, pour order 133): 3350.08,4716.33 3789.53,4716.33 3789.53,5087.32 3749.67,5127.18 3350.08,5127.18 3350.08,4871.77
ILN3 on Top Layer "TOP_LAYER_ILN3_P244" (solid, remove dead copper, pour order 244): 3432.16,3640.16 4079.64,3640.16 4114.64,3657.67 4114.64,3752.67 4079.64,3767.67 4079.64,4477.67 3804.09,4477.67 3789.09,4492.67 3789.09,4557.67 3427.1,4557.67
SW_3 on Top Layer "TOP_LAYER_SW_3_P248" (solid, remove dead copper, pour order 248): 3834.64,3152.67 3834.64,3007.67 3780.88,3007.67 3774.64,3001.42 3774.64,2962.67 3713.66,2962.67 3713.66,2902.67 3665.43,2902.67 3664.48,2957.51 3584.64,2972.67 3581.09,3059.8 3581.09,3146.21 3432.14,3295.16 3432.14,3641.43 4128.54,3641.43 4128.54,3362.67 3995,3362.67 3995,3272.67 4029.64,3272.67 4049.64,3252.67 4049.64,3172.67 3854.64,3172.67
SW_4 on Top Layer "TOP_LAYER_SW_4_P250" (solid, remove dead copper, pour order 250): 5280.42,3145.83 5280.42,3000.83 5226.66,3000.83 5220.42,2994.58 5220.42,2955.83 5159.44,2955.83 5159.44,2895.83 5111.21,2895.83 5110.26,2950.67 5030.42,2965.83 5026.87,3052.96 5026.87,3139.38 4877.92,3288.32 4877.92,3634.59 5574.32,3634.59 5574.32,3355.83 5444.36,3355.83 5444.36,3265.83 5475.42,3265.83 5495.42,3245.83 5495.42,3165.83 5300.42,3165.83
ILN4 on Top Layer "TOP_LAYER_ILN4_P251" (solid, remove dead copper, pour order 251): 4877.94,3633.32 5525.42,3633.32 5560.42,3650.83 5560.42,3745.83 5525.42,3760.83 5525.42,4470.83 5249.87,4470.83 5234.87,4485.83 5234.87,4550.83 4872.88,4550.83
LOCSEN_P4 on Top Layer "TOP_LAYER_LOCSEN_P4_P252" (solid, remove dead copper, pour order 252): 4795.42,4755 5234.87,4755 5234.87,5081.37 5195.01,5121.24 4795.42,5121.24 4795.42,4865.83
Source_4 on Top Layer "TOP_LAYER_SOURCE_4_P253" (solid, remove dead copper, pour order 253): 4795.95,5225.29 4795.95,5100.77 5235.41,5100.77 5235.41,5225.29
BATP_4 on Top Layer "TOP_LAYER_BATP_4_P264" (solid, remove dead copper, pour order 264): 5185.42,5234.5 5185.42,6125.83 4760.42,6125.83 4760.42,5234.5
AGND on AGND "AGND_AGND_P263" (solid, remove dead copper, pour order 263): 30,25 45,10 6395,10 6395,6140 6355,6180 6345,6170 25,6170
SW_4 on AGND "AGND_SW_4_P258" (solid, remove dead copper, pour order 258): 5280.42,3145.83 5280.42,3000.83 5226.66,3000.83 5220.42,2994.58 5220.42,2955.83 5159.44,2955.83 5159.44,2895.83 5111.21,2895.83 5110.26,2950.67 5030.42,2965.83 5026.87,3052.96 5026.87,3139.38 4877.92,3288.32 4877.92,3634.59 5574.32,3634.59 5574.32,3355.83 5445,3355.83 5445,3265.83 5475.42,3265.83 5495.42,3245.83 5495.42,3165.83 5300.42,3165.83
SW_2 on AGND "AGND_SW_2_P202" (solid, remove dead copper, pour order 202): 2359.64,3152.67 2359.64,3007.67 2305.88,3007.67 2299.64,3001.42 2299.64,2962.67 2238.66,2962.67 2238.66,2902.67 2190.43,2902.67 2189.48,2957.51 2109.64,2972.67 2106.09,3059.8 2106.09,3146.21 1957.14,3295.16 1957.14,3641.43 2653.54,3641.43 2653.54,3362.67 2520,3362.67 2520,3272.67 2554.64,3272.67 2574.64,3252.67 2574.64,3172.67 2379.64,3172.67
SW_3 on AGND "AGND_SW_3_P170" (solid, remove dead copper, pour order 170): 3834.64,3152.67 3834.64,3007.67 3780.88,3007.67 3774.64,3001.42 3774.64,2962.67 3713.66,2962.67 3713.66,2902.67 3665.43,2902.67 3664.48,2957.51 3584.64,2972.67 3581.09,3059.8 3581.09,3146.21 3432.14,3295.16 3432.14,3641.43 4128.54,3641.43 4128.54,3362.67 3995,3362.67 3995,3272.67 4029.64,3272.67 4049.64,3252.67 4049.64,3172.67 3854.64,3172.67
SW_1 on AGND "AGND_SW_1_P101" (solid, remove dead copper, pour order 101): 950,3156.51 950,3009.08 893.82,3009.08 890,3005.27 890,2964.08 818.54,2964.08 818.54,2900 770.12,2900 772.84,2959.79 697.57,2974.08 694.02,3061.22 694.02,3147.63 545.07,3296.58 545.07,3635 1241.48,3635 1241.48,3364.08 1110,3364.08 1110,3270 1135,3270 1162.57,3242.43 1162.57,3174.08 967.57,3174.08
SW_1 on Signal "SIGNAL_SW_1_P256" (solid, remove dead copper, pour order 256): 950,3156.51 950,3009.08 893.82,3009.08 890,3005.27 890,2964.08 818.54,2964.08 818.54,2900 770.12,2900 772.84,2959.79 697.57,2974.08 694.02,3061.22 694.02,3147.63 545.07,3296.58 545.07,3635 1241.48,3635 1241.48,3364.08 1110,3364.08 1110,3270 1135.12,3270 1162.57,3242.55 1162.57,3174.08 967.57,3174.08
SW_4 on Signal "SIGNAL_SW_4_P228" (solid, remove dead copper, pour order 228): 5280.42,3145.83 5280.42,3000.83 5226.66,3000.83 5220.42,2994.58 5220.42,2955.83 5159.44,2955.83 5159.44,2895.83 5111.21,2895.83 5110.26,2950.67 5030.42,2965.83 5026.87,3052.96 5026.87,3139.38 4877.92,3288.32 4877.92,3634.59 5574.32,3634.59 5574.32,3355.83 5445,3355.83 5445,3265.83 5475.42,3265.83 5495.42,3245.83 5495.42,3165.83 5300.42,3165.83
SW_3 on Signal "SIGNAL_SW_3_P216" (solid, remove dead copper, pour order 216): 3834.64,3152.67 3834.64,3007.67 3780.88,3007.67 3774.64,3001.42 3774.64,2962.67 3713.66,2962.67 3713.66,2902.67 3665.43,2902.67 3664.48,2957.51 3584.64,2972.67 3581.09,3059.8 3581.09,3146.21 3432.14,3295.16 3432.14,3641.43 4128.54,3641.43 4128.54,3362.67 3995,3362.67 3995,3272.67 4029.64,3272.67 4049.64,3252.67 4049.64,3172.67 3854.64,3172.67
SW_2 on Signal "SIGNAL_SW_2_P100" (solid, remove dead copper, pour order 100): 2359.64,3152.67 2359.64,3007.67 2305.88,3007.67 2299.64,3001.42 2299.64,2962.67 2238.66,2962.67 2238.66,2902.67 2190.43,2902.67 2189.48,2957.51 2109.64,2972.67 2106.09,3059.8 2106.09,3146.21 1957.14,3295.16 1957.14,3641.43 2653.54,3641.43 2653.54,3362.67 2520,3362.67 2520,3272.67 2554.64,3272.67 2574.64,3252.67 2574.64,3172.67 2379.64,3172.67
AGND on Bottom Layer "BOTTOM_LAYER_AGND_P186" (solid, remove dead copper, pour order 186): 1515,2227.77 1515,0.95 6400,0.95 6400,2227.77
PGND on Bottom Layer "BOTTOM_LAYER_PGND_P275" (solid, remove dead copper, pour order 275): 0,6173.76 0,3.76 1510.39,3.76 1519.56,1646.22 4659.4,1646.22 5224.69,2203.76 6400,2203.76 6400,6203.71
SW_4 on Bottom Layer "BOTTOM_LAYER_SW_4_P269" (solid, remove dead copper, pour order 269): 5280.42,3145.83 5280.42,3000.83 5226.66,3000.83 5220.42,2994.58 5220.42,2955.83 5159.44,2955.83 5159.44,2895.83 5111.21,2895.83 5110.26,2950.67 5030.42,2965.83 5026.87,3052.96 5026.87,3139.38 4877.92,3288.32 4877.92,3634.59 5574.32,3634.59 5574.32,3355.83 5445,3355.83 5445,3265.83 5475.42,3265.83 5495.42,3245.83 5495.42,3165.83 5300.42,3165.83
SW_3 on Bottom Layer "BOTTOM_LAYER_SW_3_P262" (solid, remove dead copper, pour order 262): 3835.38,3157.93 3835.38,3012.93 3781.63,3012.93 3775.38,3006.68 3775.38,2967.93 3714.41,2967.93 3714.41,2907.93 3666.18,2907.93 3665.23,2962.77 3585.38,2977.93 3581.84,3065.07 3581.84,3151.48 3432.89,3300.43 3432.89,3646.69 4129.29,3646.69 4129.29,3367.93 3995.75,3367.93 3995.75,3277.93 4030.38,3277.93 4050.38,3257.93 4050.38,3177.93 3855.38,3177.93
SW_2 on Bottom Layer "BOTTOM_LAYER_SW_2_P259" (solid, remove dead copper, pour order 259): 2359.64,3152.67 2359.64,3007.67 2305.88,3007.67 2299.64,3001.42 2299.64,2962.67 2238.66,2962.67 2238.66,2902.67 2190.43,2902.67 2189.48,2957.51 2109.64,2972.67 2106.09,3059.8 2106.09,3146.21 1957.14,3295.16 1957.14,3641.43 2653.54,3641.43 2653.54,3362.67 2520,3362.67 2520,3272.67 2554.64,3272.67 2574.64,3252.67 2574.64,3172.67 2379.64,3172.67
SW_1 on Bottom Layer "BOTTOM_LAYER_SW_1_P257" (solid, remove dead copper, pour order 257): 950,3156.51 950,3009.08 893.82,3009.08 890,3005.27 890,2964.08 818.54,2964.08 818.54,2900 770.12,2900 772.84,2959.79 697.57,2974.08 694.02,3061.22 694.02,3147.63 545.07,3296.58 545.07,3635 1241.48,3635 1241.48,3364.08 1110,3364.08 1110,3270 1135.12,3270 1162.57,3242.55 1162.57,3174.08 967.57,3174.08
PGND on Power "POWER_PGND_P270" (solid, remove dead copper, pour order 270): 0,6173.76 0,3.76 1510.39,3.76 1519.56,1646.22 4659.4,1646.22 5224.69,2203.76 6400,2203.76 6400,6203.71
Source_1 on Power "POWER_SOURCE_1_P222" (solid, remove dead copper, pour order 222): 454.52,5229.08 454.52,5124.49 893.97,5124.49 893.97,5229.08
SW_4 on Power "POWER_SW_4_P249" (solid, remove dead copper, pour order 249): 5280.42,3145.83 5280.42,3000.83 5226.66,3000.83 5220.42,2994.58 5220.42,2955.83 5159.44,2955.83 5159.44,2895.83 5111.21,2895.83 5110.26,2950.67 5030.42,2965.83 5026.87,3052.96 5026.87,3139.38 4877.92,3288.32 4877.92,3634.59 5574.32,3634.59 5574.32,3355.83 5445,3355.83 5445,3265.83 5475.42,3265.83 5495.42,3245.83 5495.42,3165.83 5300.42,3165.83
SW_3 on Power "POWER_SW_3_P261" (solid, remove dead copper, pour order 261): 3835.38,3157.93 3835.38,3012.93 3781.63,3012.93 3775.38,3006.68 3775.38,2967.93 3714.41,2967.93 3714.41,2907.93 3666.18,2907.93 3665.23,2962.77 3585.38,2977.93 3581.84,3065.07 3581.84,3151.48 3432.89,3300.43 3432.89,3646.69 4129.29,3646.69 4129.29,3367.93 3995.75,3367.93 3995.75,3277.93 4030.38,3277.93 4050.38,3257.93 4050.38,3177.93 3855.38,3177.93
SW_2 on Power "POWER_SW_2_P227" (solid, remove dead copper, pour order 227): 2359.64,3152.67 2359.64,3007.67 2305.88,3007.67 2299.64,3001.42 2299.64,2962.67 2238.66,2962.67 2238.66,2902.67 2190.43,2902.67 2189.48,2957.51 2109.64,2972.67 2106.09,3059.8 2106.09,3146.21 1957.14,3295.16 1957.14,3641.43 2653.54,3641.43 2653.54,3362.67 2520,3362.67 2520,3272.67 2554.64,3272.67 2574.64,3252.67 2574.64,3172.67 2379.64,3172.67
SW_1 on Power "POWER_SW_1_P212" (solid, remove dead copper, pour order 212): 950,3156.51 950,3009.08 893.82,3009.08 890,3005.27 890,2964.08 818.54,2964.08 818.54,2900 770.12,2900 772.84,2959.79 697.57,2974.08 694.02,3061.22 694.02,3147.63 545.07,3296.58 545.07,3633.9 1241.48,3633.9 1241.48,3364.08 1110,3364.08 1110,3270 1135.12,3270 1162.57,3242.55 1162.57,3174.08 967.57,3174.08
ILN1 on Power "POWER_ILN1_P108" (solid, remove dead copper, pour order 108): 536.99,3645.75 1219.52,3645.75 1219.52,3749.08 1184.52,3764.08 1184.52,4474.08 908.97,4474.08 893.97,4489.08 893.97,4554.08 531.98,4554.08
BATP_1 on Power "POWER_BATP_1_P118" (solid, remove dead copper, pour order 118): 850,5248.12 850,6139.44 425,6139.44 425,5248.12
BATP_2 on Power "POWER_BATP_2_P123" (solid, remove dead copper, pour order 123): 2264.64,5241.34 2264.64,6132.67 1839.64,6132.67 1839.64,5241.34
BATP_3 on Power "POWER_BATP_3_P184" (solid, remove dead copper, pour order 184): 3739.64,5241.34 3739.64,6132.67 3314.64,6132.67 3314.64,5241.34
BATP_4 on Power "POWER_BATP_4_P189" (solid, remove dead copper, pour order 189): 5185.42,5234.5 5185.42,6125.83 4760.42,6125.83 4760.42,5234.5
LOCSEN_P4 on Power "POWER_LOCSEN_P4_P114" (solid, remove dead copper, pour order 114): 4795.42,4755 5234.87,4755 5234.87,5081.37 5195.01,5121.24 4795.42,5121.24 4795.42,4865.83
Source_4 on Power "POWER_SOURCE_4_P117" (solid, remove dead copper, pour order 117): 4795.42,5225.83 4795.42,5101.3 5234.87,5101.3 5234.87,5225.83
Source_3 on Power "POWER_SOURCE_3_P116" (solid, remove dead copper, pour order 116): 3349.64,5232.67 3349.64,5135 3789.09,5135 3789.09,5232.67
LOCSEN_P3 on Power "POWER_LOCSEN_P3_P096" (solid, remove dead copper, pour order 96): 3349.64,4715 3789.09,4715 3789.09,5088.21 3737.15,5140.15 3349.64,5140.15 3349.64,4872.67
Source_2 on Power "POWER_SOURCE_2_P115" (solid, remove dead copper, pour order 115): 1874.64,5232.67 1874.64,5108.14 2314.09,5108.14 2314.09,5232.67
LOCSEN_P2 on Power "POWER_LOCSEN_P2_P113" (solid, remove dead copper, pour order 113): 1874.64,4724.08 2314.09,4724.08 2314.09,5088.21 2274.23,5128.07 1874.64,5128.07 1874.64,4872.67
LOCSEN_P1 on Power "POWER_LOCSEN_P1_P107" (solid, remove dead copper, pour order 107): 454.52,4750 893.97,4750 893.97,5084.63 868.6,5110 454.52,5110 454.52,4869.08
ILN4 on Power "POWER_ILN4_P112" (solid, remove dead copper, pour order 112): 4877.87,3646.33 5560.42,3646.33 5560.42,3745.83 5525.42,3760.83 5525.42,4470.83 5249.87,4470.83 5234.87,4485.83 5234.87,4550.83 4872.88,4550.83
ILN3 on Power "POWER_ILN3_P106" (solid, remove dead copper, pour order 106): 3432.1,3651.96 4103.22,3651.96 4114.64,3657.67 4114.64,3752.67 4079.64,3767.67 4079.64,4477.67 3804.09,4477.67 3789.09,4492.67 3789.09,4557.67 3427.1,4557.67
ILN2 on Power "POWER_ILN2_P110" (solid, remove dead copper, pour order 110): 1957.09,3652.24 2628.79,3652.24 2639.64,3657.67 2639.64,3752.67 2604.64,3767.67 2604.64,4477.67 2329.09,4477.67 2314.09,4492.67 2314.09,4557.67 1952.1,4557.67
V_HV on Power "V_HV_Top" (solid, remove dead copper, pour order 211): 27.16,2235.04 27.16,1290 1836.73,1290 2236.54,1660 4633.7,1660 4910.47,1936.77 5002.69,2045 4999.96,2235.04
VIN_4 on Power "POWER_VIN_4_P206" (solid, remove dead copper, pour order 206): 4917.42,2580.83 4805.42,2527.49 4805.42,2246.66 4804.58,2245.83 5495.42,2245.83 5495.42,3153.04 5290.42,3153.04 5290.42,2580.83
VIN_3 on Power "POWER_VIN_3_P236" (solid, remove dead copper, pour order 236): 3471.64,2587.67 3359.64,2534.33 3359.64,2253.5 3359.64,2246.66 4049.64,2246.66 4049.64,3159.87 3844.64,3159.87 3844.64,2587.67
VIN_2 on Power "POWER_VIN_2_P235" (solid, remove dead copper, pour order 235): 1994.88,2590.11 1882.88,2536.78 1882.88,2255.94 1882.05,2255.11 2572.88,2255.11 2572.88,3162.32 2367.88,3162.32 2367.88,2590.11
VIN_1 on Power "POWER_VIN_1_P109" (solid, remove dead copper, pour order 109): 576.52,2584.08 464.52,2530.75 464.52,2249.91 463.69,2249.08 1154.52,2249.08 1154.52,3156.29 959.97,3156.29 959.97,2584.08
AGND on PGND "PGND_AGND_P254" (solid, remove dead copper, pour order 254): 1515,2227.77 1515,0.95 6400,0.95 6400,2227.77
PGND on PGND "PGND_PGND_P268" (solid, remove dead copper, pour order 268): 0,6170 0,0 1510.39,0 1519.56,1642.46 4659.4,1642.46 5224.69,2200 6400,2200 6400,6199.95
SW_4 on PGND "PGND_SW_4_P267" (solid, remove dead copper, pour order 267): 5280.42,3145.83 5280.42,3000.83 5226.66,3000.83 5220.42,2994.58 5220.42,2955.83 5159.44,2955.83 5159.44,2895.83 5111.21,2895.83 5110.26,2950.67 5030.42,2965.83 5026.87,3052.96 5026.87,3139.38 4877.92,3288.32 4877.92,3634.59 5574.32,3634.59 5574.32,3355.83 5445,3355.83 5445,3265.83 5475.42,3265.83 5495.42,3245.83 5495.42,3165.83 5300.42,3165.83
SW_3 on PGND "PGND_SW_3_P266" (solid, remove dead copper, pour order 266): 3835.38,3157.93 3835.38,3012.93 3781.63,3012.93 3775.38,3006.68 3775.38,2967.93 3714.41,2967.93 3714.41,2907.93 3666.18,2907.93 3665.23,2962.77 3585.38,2977.93 3581.84,3065.07 3581.84,3151.48 3432.89,3300.43 3432.89,3646.69 4129.29,3646.69 4129.29,3367.93 3995.75,3367.93 3995.75,3277.93 4030.38,3277.93 4050.38,3257.93 4050.38,3177.93 3855.38,3177.93
SW_2 on PGND "PGND_SW_2_P265" (solid, remove dead copper, pour order 265): 2359.64,3152.67 2359.64,3007.67 2305.88,3007.67 2299.64,3001.42 2299.64,2962.67 2238.66,2962.67 2238.66,2902.67 2190.43,2902.67 2189.48,2957.51 2109.64,2972.67 2106.09,3059.8 2106.09,3146.21 1957.14,3295.16 1957.14,3641.43 2653.54,3641.43 2653.54,3362.67 2520,3362.67 2520,3272.67 2554.64,3272.67 2574.64,3252.67 2574.64,3172.67 2379.64,3172.67
SW_1 on PGND "PGND_SW_1_P255" (solid, remove dead copper, pour order 255): 950,3156.51 950,3009.08 893.82,3009.08 890,3005.27 890,2964.08 818.54,2964.08 818.54,2900 770.12,2900 772.84,2959.79 697.57,2974.08 694.02,3061.22 694.02,3147.63 545.07,3296.58 545.07,3635 1241.48,3635 1241.48,3364.08 1110,3364.08 1110,3270 1135.12,3270 1162.57,3242.55 1162.57,3174.08 967.57,3174.08

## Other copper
Top Layer:
  text ".Layer_Name" at 630.64,-863.8 h60
AGND:
  text ".Layer_Name" at 643.6,-881.59 h60
Signal:
  text ".Layer_Name" at 583.67,-865.06 h60
Power:
  text ".Layer_Name" at 608.82,-858.03 h60
PGND:
  text ".Layer_Name" at 647.97,-870.71 h60
Bottom Layer:
  text ".Layer_Name" at 582.81,-853.69 h60

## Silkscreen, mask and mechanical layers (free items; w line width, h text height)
Top Overlay:
  drawing of 179 lines, arcs and shapes, not listed
  text "CH3" at 3849.46,5930 h60
  text "CH4" at 5290.47,5922.86 h60
  text "CH1" at 952.05,5908.82 h60
  text "CH2" at 2324.29,5908.82 h60
  text "BAT+" at 528.92,5547.38 h60
  text "BAT-" at 1333.26,5541.33 h60
  text "BAT-" at 4285,5535.11 h60
  text "BAT+" at 3480.67,5534.01 h60
  text "BAT+" at 1995.69,5526.24 h60
  text "BAT-" at 5676.81,5525 h60
  text "BAT-" at 2717.55,5521.63 h60
  text "BAT+" at 4904.47,5521.33 h60
  text "'.PRJ_Number'.PCB_Rev" at 205,3770 h108.27 r90
  text "ACV" at 6025,2045 h60
  text "V_HV" at 858.78,1710 h60 r270
  text "LOC SNS & OCP" at 3237.75,1646.22 h60
  text "GND" at 876.58,950.52 h60 r270
  text ".Layer_Name" at 1051.17,-866.21 h60
Bottom Overlay:
  text "V_SNS" at 6011.34,2043.33 h50
  text "I_SNS" at 6348.41,1483.31 h50
  text ".Layer_Name" at 577,-858.49 h60
Top Paste:
  text ".Layer_Name" at 929.09,5774.37 h60
Bottom Paste:
  text ".Layer_Name" at 3357.32,2399.06 h60
  text ".Layer_Name" at 3357.32,2399.06 h60
  text ".Layer_Name" at 1051.17,-866.21 h60
Top Solder:
  text ".Layer_Name" at 929.09,5774.37 h60
  text ".Layer_Name" at 929.09,5774.37 h60
Bottom Solder:
  text ".Layer_Name" at 3357.32,2399.06 h60
  text ".Layer_Name" at 3357.32,2399.06 h60
  text ".Layer_Name" at 1051.17,-866.21 h60
Drill Guide:
  text ".Layer_Name" at 582.81,-853.69 h60
M1 Board Outline:
  the board outline again, w10
  text ".Layer_Name" at 577,-858.49 h60
M2 Board Dimensions:
  rectangle: 0,-275 125,-150
  rectangle: 125,-400 500,-275
  lines w7: 0,-275 1000,-275 ; 125,-400 125,-150 ; 250,-400 250,-150 ; 500,-400 500,-150 ; 750,-400 750,-150 ; 1000,-400 0,-400 0,-150 1000,-150
  text ".Layer_Name" at 577,-858.49 h60
M3 3D STEP Top:
  text ".Layer_Name" at 577,-858.49 h60
M4 3D STEP Bottom:
  text ".Layer_Name" at 577,-858.49 h60
M5 Assembly Top:
  lines w10: -292,-930.17 6308,-930.17 ; -292,-726.83 6310,-726.83 ; -292,-523.5 -292,-1133.5 3713,-1133.5 6310,-1133.5 6310,-523.5 -291.5,-523.5 -291.5,-1133.5 ; 2160,-1125 2160,-515 ; 3440,-726.83 3440,-523.5 ; 4280,-726.83 4280,-523.5 ; 4902,-1140 4902,-937.17
  text "ASSEMBLY VARIANT:" at 20,7200 h60
  text ".VariantName" at 1067.1,7198.82 h60
  text "PLOT NAME =" at 40,7065 h60
  text ".VariantName" at 5565,-310 h60
  text "COMPONENTS MARKED 'DNP' SHOULD NOT BE POPULATED." at 1153.5,-318.5 h60
  text "ASSEMBLY VARIANT:" at 4522.28,-329.6 h60
  text "BOARD #:" at 2248,-655.67 h60
  text ".PRJ_Number" at 2793.5,-655.67 h60
  text "REV:" at 3638,-655.67 h60
  text ".PCB_Rev" at 3929.5,-655.67 h60
  text "SVN REV:" at 4476,-655.67 h60
  text ".VersionControl_RevNumber" at 4982,-655.67 h60
  text "PCB VIEWED FROM TOP SIDE" at 310,-850 h60
  text "TID #:" at 2248,-859 h60
  text ".TID" at 2793.5,-859 h60
  text "GENERATED    :" at 2250,-1064.34 h60
  text ".Print_Date" at 3119.5,-1064.34 h60
  text ".Print_Time" at 3848.5,-1064.34 h60
  text "TEXAS INSTRUMENTS" at 5113,-1064.34 h60
  text ".plot_File_Name" at -100,-1075 h60
M6 Assembly Bottom:
  lines w10: -292.5,-727.33 6309.5,-727.33 ; -290.5,-930.67 6309.5,-930.67 ; 1404.31,5206.54 1404.31,5409.88 ; 2160,-935 2160,-732.17 ; 2577.5,-727.33 2577.5,-524 ; 3844.5,-1134 3844.5,-524 ; 4733.5,-1134 6309,-1134 6309,-524 -292.5,-524 -292.5,-1134 2304.5,-1134 6309.5,-1134 6309.5,-524 ; 10484.82,2131.14 10484.82,2333.97 ; 3615.82,2509.65 3615.82,2712.48 3615.82,2509.65 ; 4280.93,5232.99 4280.93,5436.32 4280.93,5232.99
  text ".PCB_Rev" at 3512.81,5685.06 h60
  text ".PCB_Rev" at 3512.81,5685.06 h60
  text "REV:" at 3773.2,5450.06 h60
  text "REV:" at 3773.2,5450.06 h60
  text "SVN REV:" at 4084.93,5304.15 h60
  text "SVN REV:" at 4084.93,5304.15 h60
  text "SVN REV:" at 1208.31,5277.71 h60
  text ".PCB_Rev" at 1953.14,4914.86 h60
  text ".Print_Time" at 1383.55,3633.11 h60
  text "COMPONENTS MARKED 'DNP' SHOULD NOT BE POPULATED." at 6102,-318 h60
  text "ASSEMBLY VARIANT:" at 6097,-434 h60
  text ".VariantName" at 5035,-445 h60
  text ".PRJ_Number" at 3224,-656.17 h60
  text "BOARD #:" at 3769.5,-656.17 h60
  text "PCB VIEWED FROM BOTTOM SIDE" at 6246,-656.17 h60
  text ".VersionControl_RevNumber" at 6250.9,-659.78 h60
  text ".VersionControl_RevNumber" at 6250.9,-659.78 h60
  text ".Print_Date" at 3109.44,-792.46 h60
  text "GENERATED    :" at 3978.94,-792.46 h60
  text ".VersionControl_RevNumber" at 6040,-830 h60
  text ".TID" at 3224,-859.5 h60
  text "TID #:" at 3769.5,-859.5 h60
  text "TEXAS INSTRUMENTS" at 1790,-1045 h60
  text ".plot_File_Name" at 5440.5,-1064.84 h60
M9 Title Sheet:
  drawing of 58 lines, arcs and shapes, not listed
  text "1" at 700,8055 h70
  text "2" at 3235.5,8036.5 h70
  text "3" at 5724.84,8036.5 h70
  text "4" at 8231.51,8036.5 h70
  text "5" at 10730.5,8036.5 h70
  text "6" at 13235.5,8036.5 h70
  text "A" at -400,7195 h70
  text "A" at 14383.5,6893.5 h70
  text "B" at -416.5,4513.5 h70
  text "B" at 14383.5,4513.5 h70
  text "C" at 14370,2195 h70
  text "C" at -415,1865 h70 r358.99
  text "PROJECT TITLE:" at 11343.5,277.5 h45
  text ".PRJ_Title" at 11393.5,144.17 h70
  text "DESIGNED FOR:" at 11343.5,-23.5 h45
  text ".PRJ_Customer" at 11393.5,-163.5 h70
  text "D" at -416.5,-231.5 h70
  text "D" at 14383.5,-231.5 h70
  text "FILE NAME:" at 11343.5,-323.5 h45
  text ".PCB_File_Name_No_Path" at 11393.5,-443.5 h70
  text "Texas Instruments (TI) and/or its licensors do not warrant the accuracy or completeness of this specification" at 6374,-605.34 h45
  text "ENGINEER:" at 11343.5,-613.5 h45
  text "LAYOUT BY:" at 12848.5,-613.5 h45
  text "or any information contained therein. TI and/or its licensors do not warrant that this design will meet" at 6329.01,-718 h45
  text ".PRJ_Engineer" at 11393.5,-768.49 h70
  text ".PCB_Layout" at 12899,-768.49 h70
  text "the specifications, will be suitable for your application or fit for any particular purpose, or will operate in" at 6329.01,-830.67 h45
  text ".Layer_Name" at 577,-858.49 h60
  text "ALTIUM DESIGNER VERSION:" at 12848.5,-923.5 h45
  text "an implementation. TI and/or its licensors do not warrant that the design is production worthy. You should" at 6329.01,-943.33 h45
  text "completely validate and test your design implementation to confirm the system functionality for your application." at 6374,-1056 h45
  text ".print_Scale" at 11393.5,-1056.83 h70
  text ".Application_BuildNumber" at 12899,-1056.83 h70
  text "3" at 5730,-1255 h70
  text "2" at 3235.5,-1263.5 h70
  text "4" at 8231.51,-1263.5 h70
  text "5" at 10730.5,-1263.5 h70
  text "6" at 13235.5,-1263.5 h70
  text "1" at 590,-1265 h70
